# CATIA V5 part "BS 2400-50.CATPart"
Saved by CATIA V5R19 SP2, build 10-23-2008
Part number: BS 2400-50
Bounding box of the stored display mesh (mm): x -37.351 to 37.351, y -37.351 to 37.351, z 0 to 145
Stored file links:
  C:\Users\Bora\Desktop\3D Katı model\BS serisi\BS 2400\BS 2400-50.CATPart
  C:\Program Files\Dassault Systemes\B19\intel_a\reffiles\standard\MetricThickPitch.txt
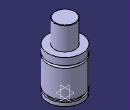
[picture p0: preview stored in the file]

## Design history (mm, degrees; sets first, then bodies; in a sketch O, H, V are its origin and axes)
Body1 (main body)
  Sketch1 on yz-plane, origin (0, 0, 0), H (0, 1, 0), V (0, 0, 1)
    point P1 (22.5, 144)
    point P3 (22.5, 144)
    point P7 (37.5, 78.5)
    point P9 (37.5, 78.5)
    point P10 (37.5, 73.5)
    point P14 (37.5, 73.5)
    line L1 (22.5, 144) -> (22.5, 94)
    arc A1 centre (21.5, 144) radius 1 from (22.5, 144) to (21.5, 145) ccw
    line L2 (37.5, 0) -> (37.5, 8)
    line L3 (37.5, 78.5) -> (37.5, 94)
    arc A2 centre (37.5, 76) radius 2.5 from (37.5, 78.5) to (37.5, 73.5) ccw
    line L4 (34.5, 13) -> (34.5, 8)
    line L5 (37.5, 13) -> (37.5, 73.5)
    line L6 (21.5, 145) -> (0, 145)
    point P15 (0, 145)
    line L7 (22.5, 94) -> (37.5, 94)
    line L8 (0, 0) -> (37.5, 0)
    line L9 (34.5, 13) -> (37.5, 13)
    line L10 (34.5, 8) -> (37.5, 8)
    coincidence: P15 V, P1 P3, P7 P9, P10 P14
    tangency: L6 A1
    horizontal: L7 H, L8 H, L9 H, L10 H
  Shaft1: profile Sketch1, axis Sketch1.V, angle 360
  Sketch2 on face of Shaft1 from Sketch1.L8, origin (0, 0, 0), H (1, 0, 0), V (0, -1, 0)
    point P1 (20, 0)
    distance P1 V = 20
  Hole1: placed by Sketch2, at (20, 0, 0) direction (0, 0, 1), diameter 6.647, depth 5, threaded "M8", thread diameter 8, thread depth 5, pitch 1.25
  CircPattern1: of Hole1, instances 4, angular step 90, axis from xy-plane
